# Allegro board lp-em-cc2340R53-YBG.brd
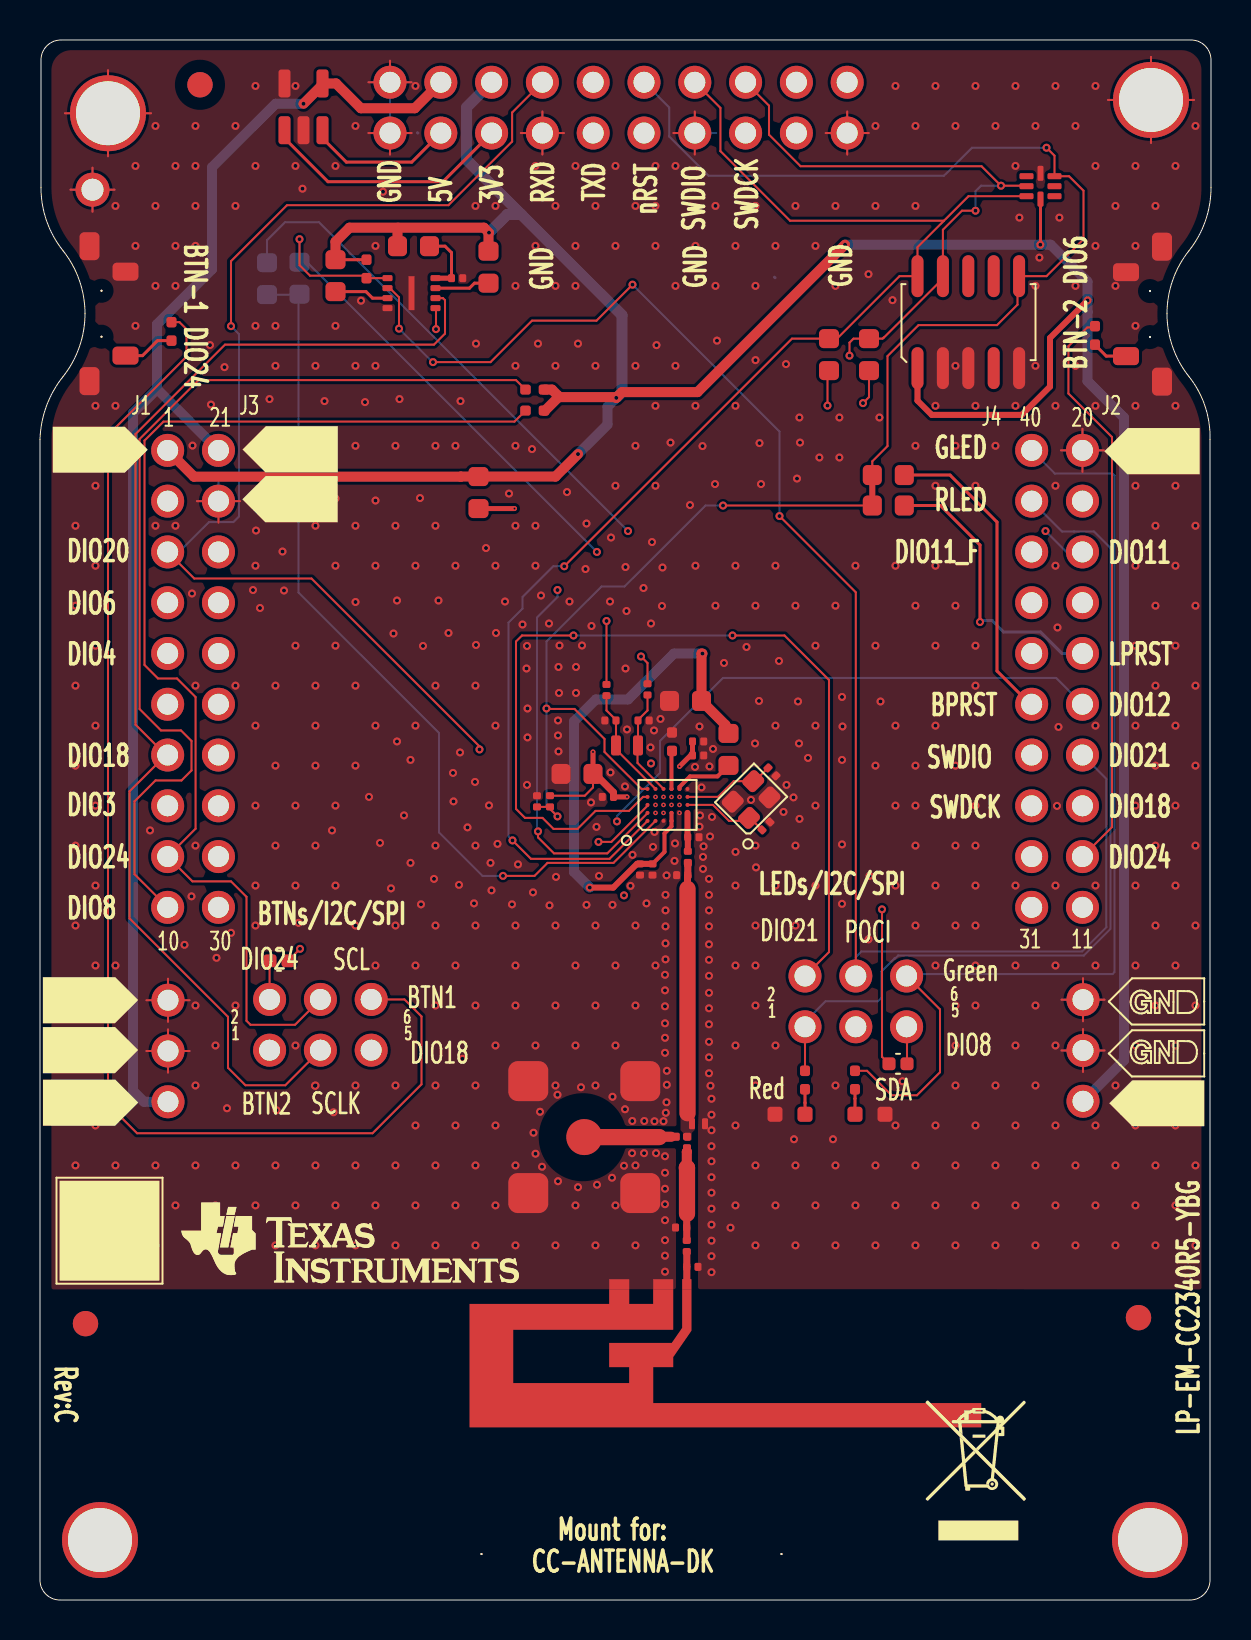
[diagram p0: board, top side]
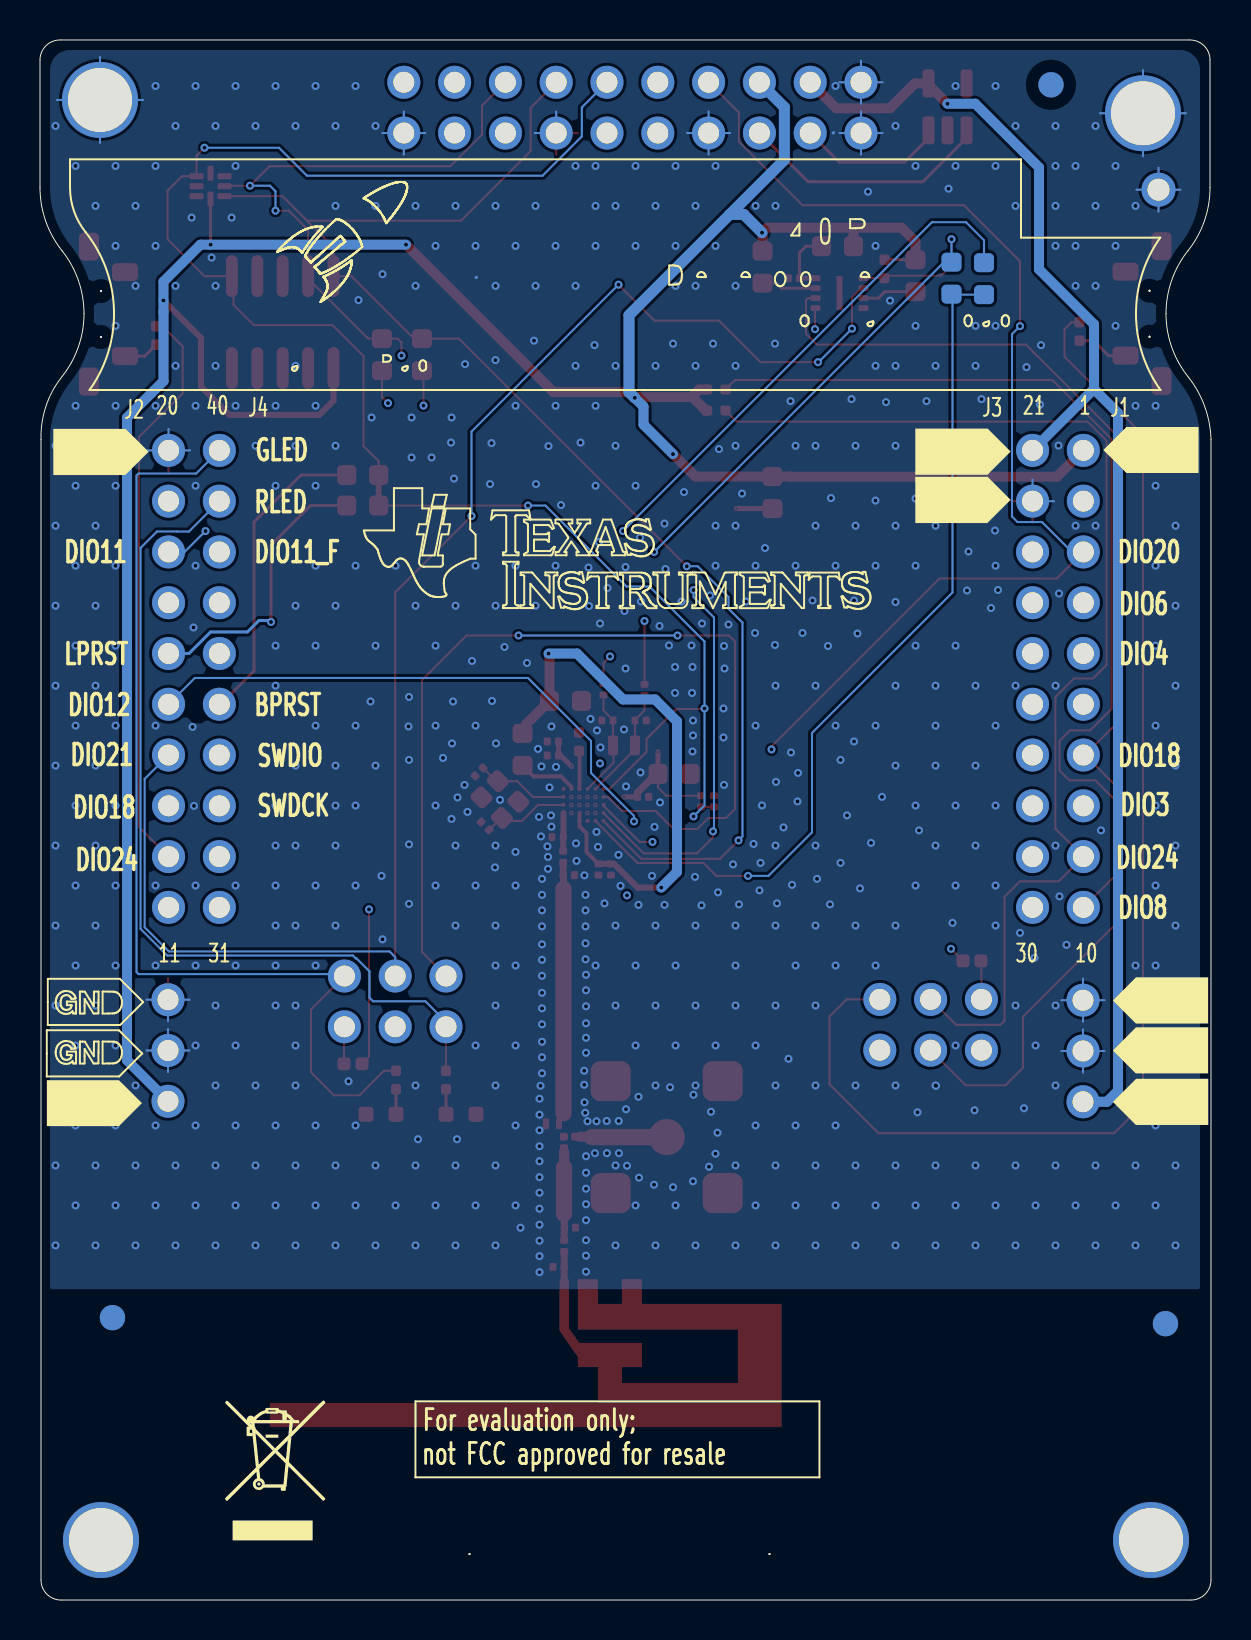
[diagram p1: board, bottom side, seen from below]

Outline 58.55 x 78.04 mm; copper layers: TOP, LAYER2, LAYER3, LAYER4, LAYER5, BOTTOM. Coordinates in mm from the lower left corner of the outline.
Outline path: 0,58.05 0,1 arc(0.29,0.29) 1,0 57.5,0 arc(58.21,0.29) 58.5,1 58.5,58.05 arc(58.25,59.72) 57.45,61.2 arc(56.63,62.68) 56.35,64.35 arc(56.63,66.02) 57.45,67.5 arc(58.27,68.98) 58.55,70.65 58.55,77.04 arc(58.26,77.75) 57.55,78.04 1.05,78.04 arc(0.34,77.75) 0.05,77.04 0.05,70.65 arc(0.33,68.98) 1.15,67.5 arc(1.97,66.02) 2.25,64.35 arc(1.97,62.68) 1.15,61.2 arc(0.32,59.72) 0,58.05

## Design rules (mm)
constraint set DEFAULT: min track width 0.102
net group BTN1: nets BTN1 N3110768
net group BTN2: nets BTN2 N3110772
net group DIO3: nets DIO3 X32_P
net group DIO4: nets DIO4 X32_N
net group DIO8_SDA: nets DIO8_SDA DIO8_SDA_T
net group DIO24_A7_SCL: nets DIO24_A7_SCL DIO24_A7_SCL_T
net group GLED: nets GLED N3110876
net group RLED: nets N3110880 RLED
net group WMCU_SWDCK: nets N3109960 WMCU_SWDCK
net group WMCU_SWDIO: nets N3109894 WMCU_SWDIO
net group BP_RESET: nets BP_RESET LP_RESET WMCU_RESET
net group DIO11_FLASH_CS: nets DIO11 DIO11_CS DIO11_FLASH_CS
net group RF: nets N3377070 RF RF_ANT RF_FILT RF_SMA

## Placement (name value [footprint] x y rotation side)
ANT1  2.4GHz  [ANTENNA_DN007AN]  32.34 15.8 180 top
B1  0  [RESC1608X55A2N]  21.93 54.6 90 top
C9  1uF  [CAPC1005X60B2N]  31.6 42.48 90 top
C33  1.5pF  [CAPC0603X35B2N]  32.95 38.16 180 top
C34  1.5pF  [CAPC0603X35B2N]  31.83 36.26 0 top
C52  7.5pF  [CAPC0603X35B2N]  36.1 38.53 45 top
C53  7.5pF  [CAPC0603X35B2N]  36.4 41.62 315 top
C55  0.1uF  [CAPC0603X35B2N]  20.57 66.12 0 top
C81  12pF  [CAPC0603X35B2N]  29.9 44 0 top
C91  15pF  [CAPC0603X35B2N]  28.8 44 180 top
C92  0.1uF  [CAPC0603X35B2N]  24.85 39.68 90 top
C101  0.1uF  [CAPC0603X35B2N]  32.62 42.95 0 top
C102  0.1uF  [CAPC0603X35B2N]  28.68 40.18 180 top
C103  0.1uF  [CAPC0603X35B2N]  32.62 42.25 0 top
C104  10uF  [CAPC1608X100A2N]  27.65 41.33 180 top
C105  10uF  [CAPC1608X100A2N]  33.07 44.98 180 top
C106  0.1uF  [CAPC0603X35B2N]  30.62 36.83 270 top
C107  0.1uF  [CAPC0603X35B2N]  30 36.83 270 top
CA1  15pF  [CAPC0603X35B2N]  32.38 23.18 180 top
CA2  15pF  [CAPC0603X35B2N]  32.35 22.62 90 top
CR1  LPL296-J2L2-25  [LEDC1707X65N]  42.25 24.3 180 top
CR2  LS L296-P2Q2-1  [LEDC1708X67N]  36.75 24.3 0 top
CR8  TPD6E004RSE  [QFNFC50P150X150X60-8A2N]  50.72 70.23 90 top
CR10  TPD1E0B04DPY  [SON65P100X60X45-2A2N]  33.25 23.83 180 top
FIDU1  FIDU_1.27mm  [FID127X142]  8 75.8 0 top
FIDU2  FIDU_1.27mm  [FID127X142]  2.28 13.83 0 top
FIDU3  FIDU_1.27mm  [FID127X142]  54.93 14.12 0 top
FIDU4  FIDU_1.27mm  [FID127X142]  8 75.8 180 bottom
FIDU5  FIDU_1.27mm  [FID127X142]  2.28 13.83 180 bottom
FIDU6  FIDU_1.27mm  [FID127X142]  54.93 14.12 180 bottom
J1  SSQ-110-23-L-D  [SAMTEC_SSQ11023LD_A2B]  6.38 57.51 0 bottom
J2  SSQ-110-23-L-D  [SAMTEC_SSQ11023LD_A2B]  49.58 57.51 0 bottom
J7  SMA-10V21-TGG  [HUSTSAN_SMA10V21TGGAN]  27.21 23.16 0 top
L1  10uH  [INDC1608X100A2N]  34.43 43.35 270 top
L33  2.8nH  [INDC0603X33A2N]  32.39 37.46 270 top
LBL1  TI_LOGO  [TI_LOGO_1]  8.06 19.89 0 top
LBL2  TRASH_7mm  [TRASH_7MM]  44.92 2.98 0 top
LBL3  ESD_LABEL_5x5mm  [ESD_LABEL_5X5]  0.97 15.98 0 top
LBL5  -  [LABEL_FOR_EVALUATION_ONLY]  39.63 6.29 180 bottom
M1  SNT-100-BK-G  [SAMTEC_SNT100BKG]  39.5 27.43 90 top
M2  SNT-100-BK-G  [SAMTEC_SNT100BKG]  44.6 27.38 90 top
M3  DCB-12D  [MECH_DCB12D_A2B]  3 3 0 top
M4  DCB-12D  [MECH_DCB12D_A2B]  55.5 3 0 top
M5  DCB-12D  [MECH_DCB12D_A2B]  3.38 75.2 0 top
M6  DCB-12D  [MECH_DCB12D_A2B]  55.53 75.04 0 top
M7  SNT-100-BK-G  [SAMTEC_SNT100BKG]  12.75 26.2 90 top
M8  SNT-100-BK-G  [SAMTEC_SNT100BKG]  17.82 26.2 90 top
MH1  HOLE_3.2mm_PAD_3.8mm_PTH  [MTG320_380]  3 3 0 top
MH2  HOLE_3.2mm_PAD_3.8mm_PTH  [MTG320_380]  55.5 3 0 top
MH3  HOLE_3.2mm_PAD_3.8mm_PTH  [MTG320_380]  3.4 74.38 0 top
MH4  HOLE_3.2mm_PAD_3.8mm_PTH  [MTG320_380]  55.55 75.04 0 top
MH5  HOLE_1.1mm_PTH  [MTG110_170]  2.62 70.55 0 top
NOREF  #VALUE  [unnamed]  22.07 2.3 0 top
NOREF#2  -  [#2]  0.05 75.03 0 top
NOREF#3  -  [#2]  -2.23 77.42 0 top
NOREF#4  -  [#2]  -2.31 22.34 0 top
NOREF#5  -  [#2]  0.9 -39.72 0 top
NOREF#6  -  [#2]  -4.3 56.35 0 top
NOREF#7  -  [#2]  0.28 64.51 0 top
NOREF#8  -  [#2]  53.24 23.47 0 top
NOREF#9  -  [#2]  -45.6 -63.8 0 top
NOREF#10  -  [#2]  53.15 0 90 top
NOREF#11  -  [#2]  8.4 52.65 0 top
NOREF#12  -  [#2]  51.5 55.05 0 top
NOREF#13  -  [#2]  -2.18 25.12 0 top
NOREF#14  -  [#2]  0.34 77.74 0 top
NOREF#15  -  [#2]  -2.18 27.62 0 top
NOREF#16  -  [#2]  8.46 55.02 0 top
NOREF#17  -  [#2]  60.2 55.05 180 bottom
NOREF#18  -  [#2]  6.57 22.38 180 bottom
NOREF#19  -  [#2]  17.24 54.91 180 bottom
NOREF#20  -  [#2]  58.27 23.64 180 bottom
NOREF#21  -  [#2]  6.62 25.08 180 bottom
NOREF#22  -  [#2]  6.62 27.58 180 bottom
NOREF#23  -  [#2]  116.69 68.47 180 bottom
NOREF#24  -  [#2]  51.53 78.57 180 bottom
NOREF#25  -  [#2]  5.6 56.15 180 bottom
NOREF#26  -  [#2]  17.1 52.65 180 bottom
P1  BB02-HC031-KB1-603000  [GRADCONN_BB02HC031KB1603000_A2B]  52.15 24.95 90 top
P2  BB02-HJ061-KB1-603000  [GRADCONN_BB02HJ061KB1603000_A2B]  38.25 28.68 0 top
P3  CNT-F254-210-GD-850/3.2  [CNT_CNTF254210GD85032_A2B]  17.5 75.93 0 top
P4  FTSH-105-01-F-DV-K  [SAMTEC_FTSH-105-01-F-DV-K-10N]  43.88 61.62 0 top
P5  BB02-HC031-KB1-603000  [GRADCONN_BB02HC031KB1603000_A2B]  6.4 24.93 90 top
P6  BB02-HJ061-KB1-603000  [GRADCONN_BB02HJ061KB1603000_A2B]  11.48 27.51 0 top
R1  100k  [RESC0603X35B2N]  25.5 39.68 90 top
R4  0  [RESC1608X55A2N]  39.45 61.5 90 top
R5  0  [RESC1608X55A2N]  41.45 61.5 90 top
R6  0  [RESC0603X35B2N]  30.38 45.28 90 top
R7  0  [RESC0603X35B2N]  28.32 45.8 270 top
R14  180  [RESC1005X40B2N]  38.25 25.55 90 top
R15  220  [RESC1005X40B2N]  40.75 25.55 90 top
R19  0  [RESC1608X55A2N]  11.35 65.3 90 bottom
R20  0  [RESC1608X55A2N]  12.97 65.33 90 bottom
R22  0  [RESC1608X55A2N]  22.43 67.48 270 top
R23  0  [RESC1608X55A2N]  14.78 67.05 270 top
R24  2.2k  [RESC1005X40B2N]  16.32 66.12 90 top
R25  0  [RESC1608X55A2N]  19.47 67.73 180 top
R51  0  [RESC1608X55A2N]  43.22 54.75 180 top
R52  0  [RESC1608X55A2N]  43.22 56.28 180 top
R55  100  [RESC1005X40B2N]  52.75 62.8 90 top
R56  100  [RESC1005X40B2N]  6.57 63 90 top
R66  3.3k  [RESC1005X40B2N]  24.28 60.55 0 top
R67  3.3k  [RESC1005X40B2N]  24.28 59.5 0 top
R68  0  [RESC1005X40A2N]  11.5 31.98 0 top
R69  0  [RESC1005X40A2N]  42.45 26.83 0 top
SW1  1188E-1K2  [SW_1188E1K2V_A2N]  2.47 67.73 270 top
SW2  1188E-1K2  [SW_1188E1K2V_A2N]  56.1 60.95 90 top
U1  CC2340R53E0YBG  [BGAFC28C40P260X219X50]  30.38 38.98 0 top
U3  MX25R8035FZUIL0  [SON50P300X200X60-9B2N]  17.38 66.12 270 top
U4  CAT24C08TDI  [SOT95P280X100-5A2N]  12.22 73.53 0 top
UNK#REFDES  #VALUE  [#2]  46.65 66.21 180 bottom
Y1  32.768KHz  [XTAL_TZ3359DAAO73_A2N]  29.9 42.75 180 top
Y2  48MHz  [OSCCC205X165X50-4A2N]  35.45 39.12 45 top
Z60  12pF  [CAPC0603X35B2N]  32.34 18.63 180 top
Z61  0  [RESC0603X35B2N]  32.34 17.43 90 top
Z62  12pF  [CAPC0603X35B2N]  32.34 16.67 0 top

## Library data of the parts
ANT1 = ANTENNA_DN007
B1 R4 R5 R19 R20 R22 R23 R25 R51 R52 = RESISTOR: User Part Number: #PN; alternate symbols: (RESC1608X55A2L,RESC1608X55A2M)
C9 = CAPACITOR: User Part Number: #PN; alternate symbols: (CAPC1005X60A2L,CAPC1005X60A2M)
C33 C34 C52 C53 C55 C81 C91 C92 C101-C103 C106 C107 CA1 CA2 Z60 Z62 = CAPACITOR: User Part Number: #PN; alternate symbols: (CAPC0603X35B2L,CAPC0603X35B2M)
C104 C105 = CAPACITOR: User Part Number: #PN; alternate symbols: (CAPC1608X100A2L,CAPC1608X100A2M)
CR1 = LED: alternate symbols: (LEDC1707X65L,LEDC1707X65M)
CR2 = LED: alternate symbols: (LEDC1708X67L,LEDC1708X67M)
CR8 = DIODE_TVS_TPD6E004_QFN8_V1: User Part Number: #PN; alternate symbols: (QFNFC50P150X150X60-8A2L,QFNFC50P150X150X60-8A2M)
CR10 = DIODE_TVS_BIDIR_S_0: User Part Number: #PN
FIDU1-FIDU6 = FIDMARK
J1 J2 = CONN_HEADER_2X10_J_S_V1: User Part Number: #PN; alternate symbols: (SAMTEC_SSQ11023LD_A2A,SAMTEC_SSQ11023LD_A2C)
J7 = CONN_COAX_1_4: alternate symbols: (HUSTSAN_SMA10V21TGGL,HUSTSAN_SMA10V21TGGM)
L1 = IND_CORE: User Part Number: #PN; alternate symbols: (INDC1608X100A2L,INDC1608X100A2M)
L33 = INDUCTOR: User Part Number: #PN; alternate symbols: (INDC0603X33A2L,INDC0603X33A2M)
LBL1 = TI_LOGO_V1
LBL2 = TRASH_V2: User Part Number: #PN
LBL3 = ESD_LABEL: User Part Number: #PN
LBL5 = LABEL_FOR_EVALUATOIN_ONLY: User Part Number: #PN
M1 M2 M7 M8 = MECH_SHUNT_JUMPER_V1: User Part Number: #PN
M3-M6 = MECH_SPACERS_SUPPORT_V1: User Part Number: #PN
MH1-MH5 = HOLE_PTH
NOREF UNK#REFDES = -: User Part Number: #PN
P1 P5 = CONN_HEADER_3_P_S: User Part Number: #PN; alternate symbols: (GRADCONN_BB02HC031KB1603000_A2A,GRADCONN_BB02HC031KB1603000_A2C)
P2 P6 = CONN_HEADER_2X3_P_V2: User Part Number: #PN; alternate symbols: (GRADCONN_BB02HJ061KB1603000_A2A,GRADCONN_BB02HJ061KB1603000_A2C)
P3 = CONN_HEADER_2X10_J_S_V1: User Part Number: #PN; alternate symbols: (CNT_CNTF254210GD85032_A2A,CNT_CNTF254210GD85032_A2C)
P4 = CONN_HEADER_2X5: alternate symbols: (SAMTEC_FTSH10501FDVK_A2L,SAMTEC_FTSH10501FDVK_A2M,SAMTEC_FTSH10501FDVK_B2L,SAMTEC_FTSH10501FDVK_B2M)
R1 R6 R7 Z61 = RESISTOR: User Part Number: #PN; alternate symbols: (RESC0603X35B2L,RESC0603X35B2M)
R14 R15 R24 R55 R56 R66 R67 = RESISTOR: User Part Number: #PN
R68 R69 = RESISTOR: User Part Number: #PN; alternate symbols: (RESC1005X40A2L,RESC1005X40A2M)
SW1 SW2 = SWITCH_TACT_V2: alternate symbols: (SW_1188E1K2V_A2L,SW_1188E1K2V_A2M)
U1 = IC_CC2340R5_DSBGA28_V1: User Part Number: #PN
U3 = IC_FLASH_MX25R8035F_USON8: User Part Number: #PN; alternate symbols: (SON50P300X200X60-9B2L,SON50P300X200X60-9B2M)
U4 = IC_EEPROM_CAT24C08_TSOT23-5: User Part Number: #PN; alternate symbols: (SOT95P280X100-5A2L,SOT95P280X100-5A2M)
Y1 = XTAL: User Part Number: #PN; alternate symbols: (XTAL_TZ3359DAAO73_A2L,XTAL_TZ3359DAAO73_A2M)
Y2 = XTAL_4PINS_1_3: User Part Number: #PN; alternate symbols: (OSCCC205X165X50-4A2L,OSCCC205X165X50-4A2M)

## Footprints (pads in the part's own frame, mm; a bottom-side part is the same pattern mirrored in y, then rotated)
ANTENNA_DN007AN
  rect 0.46x0.5 smd: 1(0,0)
  rect 1x0.5 smd: 2(1.18,0) 3(3.38,0)
BGAFC28C40P260X219X50
  round 0.2 smd: A1(0,0) A2(0,0.4) A3(0,0.8) A4(0,1.2) A5(0,1.6) B1(0.4,0) B2(0.4,0.4) B3(0.4,0.8) B4(0.4,1.2) B5(0.4,1.6) C1(0.8,0) C2(0.8,0.4) C3(0.8,0.8) C4(0.8,1.2) C5(0.8,1.6) D1(1.2,0) D2(1.2,0.4) D3(1.2,0.8) D4(1.2,1.2) D5(1.2,1.6) E2(1.6,0.4) E3(1.6,0.8) E4(1.6,1.2) E5(1.6,1.6) F2(2,0.4) F3(2,0.8) F4(2,1.2) F5(2,1.6)
CAPC0603X35B2N
  custom 0.087x0.087 smd: 1(0,0) 2(0.56,0)
CAPC1005X60B2N
  custom 0.125x0.125 smd: 1(0,0) 2(0.924,0)
CAPC1608X100A2N
  custom 0.237x0.237 smd: 1(0,0) 2(1.6,0)
CNT_CNTF254210GD85032_A2B
  round 1.65 hole 1.05: 1(0,0) 2(0,-2.54) 3(2.54,0) 4(2.54,-2.54) 5(5.08,0) 6(5.08,-2.54) 7(7.62,0) 8(7.62,-2.54) 9(10.16,0) 10(10.16,-2.54) 11(12.7,0) 12(12.7,-2.54) 13(15.24,0) 14(15.24,-2.54) 15(17.78,0) 16(17.78,-2.54) 17(20.32,0) 18(20.32,-2.54) 19(22.86,0) 20(22.86,-2.54)
FID127X142
  round 1.27 smd: 1(0,0)
GRADCONN_BB02HC031KB1603000_A2B
  round 1.65 hole 1.05: 1(0,0) 2(2.54,0) 3(5.08,0)
GRADCONN_BB02HJ061KB1603000_A2B
  round 1.65 hole 1.05: 1(0,0) 2(0,2.54) 3(2.54,0) 4(2.54,2.54) 5(5.08,0) 6(5.08,2.54)
HUSTSAN_SMA10V21TGGAN
  round 1.8 smd: 1(0,0)
  custom 0.5x0.5 smd: 2(-2.8,-2.8) 3(2.8,-2.8) 4(2.8,2.8) 5(-2.8,2.8)
INDC0603X33A2N
  custom 0.087x0.087 smd: 1(0,0) 2(0.56,0)
INDC1608X100A2N
  custom 0.237x0.237 smd: 1(0,0) 2(1.6,0)
LEDC1707X65N
  custom 0.188x0.188 smd: 1(0,0) 2(1.501,0)
LEDC1708X67N
  custom 0.188x0.188 smd: 1(0,0) 2(1.501,0)
MTG110_170
  round 1.7 hole 1.1: 1(0,0)
MTG320_380
  round 3.8 hole 3.2: 1(0,0)
OSCCC205X165X50-4A2N
  custom 0.212x0.212 smd: 1(0,0) 2(1.45,0) 3(1.45,1.15) 4(0,1.15)
QFNFC50P150X150X60-8A2N
  custom 0.075x0.075 smd: 1(0,0) 2(0.5,0) 3(1,0) 4(1.145,0.7) 5(1,1.4) 6(0.5,1.4) 7(0,1.4) 8(-0.145,0.7)
RESC0603X35B2N
  custom 0.087x0.087 smd: 1(0,0) 2(0.56,0)
RESC1005X40A2N
  custom 0.16x0.16 smd: 1(0,0) 2(0.9,0)
RESC1005X40B2N
  custom 0.125x0.125 smd: 1(0,0) 2(0.924,0)
RESC1608X55A2N
  custom 0.237x0.237 smd: 1(0,0) 2(1.6,0)
SAMTEC_FTSH-105-01-F-DV-K-10N
  oval 0.6x2.1 smd: 1(0,0) 2(0,4.6) 3(1.27,0) 4(1.27,4.6) 5(2.54,0) 6(2.54,4.6) 7(3.81,0) 8(3.81,4.6) 9(5.08,0) 10(5.08,4.6)
SAMTEC_SSQ11023LD_A2B
  round 1.65 hole 1.05: 1(0,0) 2(2.54,0) 3(0,2.54) 4(2.54,2.54) 5(0,5.08) 6(2.54,5.08) 7(0,7.62) 8(2.54,7.62) 9(0,10.16) 10(2.54,10.16) 11(0,12.7) 12(2.54,12.7) 13(0,15.24) 14(2.54,15.24) 15(0,17.78) 16(2.54,17.78) 17(0,20.32) 18(2.54,20.32) 19(0,22.86) 20(2.54,22.86)
SON50P300X200X60-9B2N
  custom 0.075x0.075 smd: 1(0,0) 2(0.5,0) 3(1,0) 4(1.5,0) 5(1.5,2.4) 6(1,2.4) 7(0.5,2.4) 8(0,2.4)
  rect 1.7x0.3 smd: 9(0.75,1.2)
SON65P100X60X45-2A2N
  custom 0.075x0.075 smd: 1(0,0) 2(0.65,0)
SOT95P280X100-5A2N
  custom 0.15x0.15 smd: 1(0,0) 2(0.95,0) 3(1.9,0) 4(1.9,2.34) 5(0,2.34)
SW_1188E1K2V_A2N
  round 0.1 hole 0.9 unplated: (2.229,0.6) (4.529,0.6)
  custom 0.25x0.25 smd: 1(0,0) 2(6.75,0)
  custom 0.225x0.225 smd: 3(1.275,1.8) 4(5.475,1.8)
unnamed
  round 0.1 hole 3.2 unplated: (0,0) (15,0)
XTAL_TZ3359DAAO73_A2N
  custom 0.125x0.125 smd: 1(0,0) 2(1.1,0)

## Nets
5V0_BP: J1.2 P3.3 P5.1 U4.4
GND: ANT1.2 ANT1.3(\GND_3\) C9.2 C33.1 C34.1 C52.2 C53.2 C55.2 C81.2 C91.2 C92.2 C101.2 C102.2 C103.2 C104.2 C105.2 C106.2 C107.2 CR1.1(\C\) CR2.1(\C\) CR8.4 CR10.1 J1.4 J2.2 J7.2 J7.3 J7.4 J7.5 MH3.1 MH4.1 MH5.1 P1.2 P1.3 P3.1 P3.2 P3.8 P3.14 P3.20 P4.3 P4.5 P4.9 P5.2 P5.3 SW1.1 SW1.2 SW1.3 SW2.1 SW2.2 SW2.4 U1.C1 U1.C3 U1.D4 U1.E2 U1.F5 U3.4 U3.9 U4.2 U4.5(\WP\) Y2.2 Y2.4(\GND#4\) Z60.2 Z62.2
VDDD: C9.1 U1.D5
VDDR: C105.1 C106.1 C107.1 L1.1 U1.D1 U1.D2
VDDS: B1.1 C101.1 C102.1 C103.1 C104.1 R1.2 U1.B4 U1.E3 U1.E4
BP_RESET: J2.11 R52.1
BTN1: J2.16 P6.6 R56.2
BTN2: J2.18 P6.1 R55.2
DCDC: L1.2 U1.E5
DIO3: J1.15 R6.2
DIO4: J1.9 R7.1
DIO8_SDA: P2.5 R69.2
DIO8_SDA_T: R69.1 U1.C2(\DIO8\)
DIO11: R19.1 R20.1 U1.B1
DIO11_CS: J2.6 R19.2
DIO11_FLASH_CS: J2.5 R20.2 R24.1 U3.1
DIO12_PICO: J2.12 U1.B2 U3.5
DIO18_SCLK: P6.5 U1.B3
DIO21_A10_POCI: P2.2 U1.A4
DIO24_A7_SCL: P6.2 R68.1
DIO24_A7_SCL_T: R68.2 U1.C4
GLED: J2.1 P2.6 R15.2
LP_RESET: J2.10 R51.1
POCI: J2.14 P2.4 U3.2
RF: C33.2 L33.1 U1.F2
RF_ANT: CA2.1 Z60.1 Z61.2
RF_FILT: C34.2 CA1.1 CA2.2 CR10.2 L33.2
RF_SMA: CA1.2 J7.1
RLED: J2.3 P2.1 R14.2
SCL: J1.17 P6.4 R67.1
SCLK: J1.13 P6.3 U3.6
SDA: J1.19 P2.3 R66.1
WMCU_RESET: C92.1 CR8.3 P3.11 P4.10 R1.1 R51.2 R52.2 U1.A5
WMCU_RXD: J1.5 P3.7 U1.A3
WMCU_SWDCK: CR8.6 P3.15 P4.4 R5.2 U1.A2
WMCU_SWDIO: CR8.7 P3.13 P4.2 R4.2 U1.A1
WMCU_TXD: J1.7 P3.9 U1.D3
WMCU_VDD: B1.2 CR8.8(\VCC\) J1.1 P1.1 P3.5 P4.1 R22.1 R23.1 R24.2 R25.2 R66.2 R67.2
X32_N: C91.1 R7.2 U1.B5 Y1.2
X32_P: C81.1 R6.1 U1.C5 Y1.1
X48_N: C52.1 U1.F3 Y2.1
X48_P: C53.1 U1.F4 Y2.3
XDS_BOARDID_SCL: P3.6 U4.1
XDS_BOARDID_SDA: P3.4 U4.3
N3109894: J2.13 R4.1
N3109960: J2.15 R5.1
N3110768: R56.1 SW1.4
N3110772: R55.1 SW2.3
N3110876: CR1.2 R15.1
N3110880: CR2.2 R14.1
N3111246: C55.1 R25.1 U3.8(\VCC\)
N3111262: R22.2 U3.7
N3111266: R23.2 U3.3
N3377070: ANT1.1 Z61.1 Z62.1

Pads without a net: CR8 1 2 5; FIDU1 1; FIDU2 1; FIDU3 1; FIDU4 1; FIDU5 1; FIDU6 1; J1 3 6 8 10 11 12 14 16 18 20; J2 4 7 8 9 17 19 20; MH1 1; MH2 1; P3 10 12 16 17 18 19; P4 6 7 8

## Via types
v1: diameter 0.4, hole 0.2, TOP to BOTTOM, 722 vias
v2: diameter 0.23, hole 0.1, TOP to LAYER2, 15 vias
v3: diameter 0.23, hole 0.1, LAYER2 to LAYER3, 10 vias

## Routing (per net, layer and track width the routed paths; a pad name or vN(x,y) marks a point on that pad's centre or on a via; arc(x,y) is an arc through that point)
5V0_BP: length 68.4
  TOP w0.5: P3.3 18.74,74.62 16.04,74.62 14.8,75.87 U4.4 14.12,75.8 v1(13.18,74.85)
  BOTTOM w0.5: P5.1 5.2,24.93 4.65,25.47 4.65,59.38 5.85,60.58 5.85,60.58 ; v1(13.18,74.85) 11.78,74.85 8.6,71.67 8.6,66.57 5.85,63.82 5.85,60.58 ; 5.85,60.58 J1.2
GND: length 402.3
  TOP w0.102: P5.3 7.48,30.01 ; P5.3 6.4,31.08 ; P5.3 6.4,28.93 ; P5.3 5.32,30.01 ; MH4.1 57.7,75.04 ; MH4.1 53.4,75.04 ; MH4.1 55.55,72.89 ; MH4.1 55.55,77.19 ; 24.04,73.38 P3.8 ; P3.8 25.12,74.46 ; P3.8 26.2,73.38 ; P3.8 25.12,72.31 ; 3.4,72.22 MH3.1 ; MH3.1 5.55,74.38 ; MH3.1 1.25,74.38 ; MH3.1 3.4,76.53 ; P1.2 53.23,27.49 ; P1.2 51.07,27.49 ; P1.2 52.15,26.41 ; P1.2 52.15,28.57 ; J2.2 53.2,57.51 ; J2.2 52.12,56.43 ; J2.2 51.05,57.51 ; J2.2 52.12,58.59 ; 29.62,23.98 29.61,23.96 v1(29.61,23.96) ; J1.4 10,54.97 ; J1.4 7.85,54.97 ; J1.4 8.92,53.89 ; P3.14 32.74,74.46 ; P3.14 32.74,72.31 ; P3.14 31.66,73.38 ; MH5.1 3.73,70.55 ; MH5.1 2.62,71.65 ; MH5.1 1.52,70.55 ; MH5.1 2.62,69.45 ; 6.4,26.39 P5.2 ; P5.2 7.48,27.47 ; P5.2 5.32,27.47 ; P5.2 6.4,28.54 ; P1.3 53.23,30.03 ; P1.3 52.15,28.95 ; P1.3 51.07,30.03 ; P1.3 52.15,31.11 ; P3.20 40.36,74.46 ; P3.20 40.36,72.31 ; P3.20 41.44,73.38 ; P3.20 39.28,73.38 ; 17.5,72.31 P3.2 ; P3.2 16.42,73.38 ; P3.2 18.58,73.38 ; P3.1 18.58,75.93 ; P3.1 16.42,75.93 ; P3.1 17.5,77
  LAYER2 w0.102: 39.28,73.38 P3.20 ; P3.20 41.44,73.38 ; P3.20 40.36,74.46 ; P3.20 40.36,72.31 ; v2(31.97,39.38) 31.57,39.38 v3(31.18,39.78) v2(31.57,40.18) ; P3.14 32.74,74.46 ; P3.14 31.66,73.38 ; P3.14 33.82,73.38 ; P3.14 32.74,72.31 ; 25.12,72.31 P3.8 ; P3.8 24.04,73.38 ; P3.8 25.12,74.46 ; P3.8 26.2,73.38 ; 52.15,28.95 P1.3 ; P1.3 53.23,30.03 ; P1.3 51.07,30.03 ; P1.3 52.15,31.11 ; J1.4 8.92,56.05 ; J1.4 10,54.97 ; J1.4 7.85,54.97 ; J1.4 8.92,53.89 ; J2.2 53.2,57.51 ; J2.2 52.12,56.43 ; J2.2 52.12,58.59 ; J2.2 51.05,57.51 ; MH3.1 5.55,74.38 ; MH3.1 1.25,74.38 ; MH3.1 3.4,76.53 ; MH3.1 3.4,72.22 ; MH5.1 3.73,70.55 ; MH5.1 1.52,70.55 ; MH5.1 2.62,69.45 ; MH5.1 2.62,71.65 ; P5.3 6.4,31.08 ; P5.3 7.48,30.01 ; P5.3 5.32,30.01 ; P5.3 6.4,28.93 ; P5.2 6.4,28.54 ; P5.2 6.4,26.39 ; P5.2 5.32,27.47 ; P5.2 7.48,27.47 ; MH4.1 57.7,75.04 ; MH4.1 53.4,75.04 ; MH4.1 55.55,72.89 ; MH4.1 55.55,77.19 ; P3.1 17.5,77 ; P3.1 18.58,75.93 ; P3.1 16.42,75.93 ; P3.1 17.5,74.85 ; P3.2 17.5,74.46 ; P3.2 16.42,73.38 ; P3.2 17.5,72.31 ; P3.2 18.58,73.38 ; P1.2 53.23,27.49 ; P1.2 51.07,27.49 ; P1.2 52.15,28.57 ; P1.2 52.15,26.41
  LAYER3 w0.102: P5.3 6.4,31.08 ; P5.3 5.32,30.01 ; P5.3 7.48,30.01 ; P5.3 6.4,28.93 ; 16.42,75.93 P3.1 ; P3.1 17.5,77 ; P3.1 17.5,74.85 ; P3.1 18.58,75.93 ; MH3.1 5.55,74.38 ; MH3.1 1.25,74.38 ; MH3.1 3.4,76.53 ; MH3.1 3.4,72.22 ; P3.8 26.2,73.38 ; P3.8 24.04,73.38 ; P3.8 25.12,72.31 ; P3.8 25.12,74.46 ; 51.05,57.51 J2.2 ; J2.2 53.2,57.51 ; J2.2 52.12,58.59 ; J2.2 52.12,56.43 ; P3.2 17.5,74.46 ; P3.2 16.42,73.38 ; P3.2 17.5,72.31 ; P3.2 18.58,73.38 ; P3.20 41.44,73.38 ; P3.20 39.28,73.38 ; P3.20 40.36,74.46 ; P3.20 40.36,72.31 ; MH5.1 3.73,70.55 ; MH5.1 2.62,69.45 ; MH5.1 2.62,71.65 ; MH5.1 1.52,70.55 ; P3.14 33.82,73.38 ; P3.14 32.74,74.46 ; P3.14 32.74,72.31 ; P3.14 31.66,73.38 ; MH4.1 57.7,75.04 ; MH4.1 55.55,72.89 ; MH4.1 55.55,77.19 ; MH4.1 53.4,75.04 ; 7.85,54.97 J1.4 ; J1.4 8.92,56.05 ; J1.4 10,54.97 ; J1.4 8.92,53.89 ; 52.15,26.41 P1.2 ; P1.2 51.07,27.49 ; P1.2 52.15,28.57 ; P1.2 53.23,27.49 ; P5.2 7.48,27.47 ; P5.2 5.32,27.47 ; P5.2 6.4,26.39 ; P5.2 6.4,28.54 ; 52.15,28.95 P1.3 ; P1.3 51.07,30.03 ; P1.3 53.23,30.03 ; P1.3 52.15,31.11
  LAYER4 w0.102: 1.25,74.38 MH3.1 ; MH3.1 5.55,74.38 ; MH3.1 3.4,72.22 ; MH3.1 3.4,76.53 ; 17.5,72.31 P3.2 ; P3.2 17.5,74.46 ; P3.2 16.42,73.38 ; P3.2 18.58,73.38 ; P3.20 41.44,73.38 ; P3.20 40.36,74.46 ; P3.20 39.28,73.38 ; P3.20 40.36,72.31 ; 25.12,72.31 P3.8 26.2,73.38 ; J1.4 8.92,56.05 ; J1.4 8.92,53.89 ; J1.4 10,54.97 ; J1.4 7.85,54.97 ; P3.1 18.58,75.93 ; P3.1 16.42,75.93 ; P3.1 17.5,77 ; P3.1 17.5,74.85 ; 5.32,27.47 P5.2 ; P5.2 7.48,27.47 ; P5.2 6.4,26.39 ; P5.2 6.4,28.54 ; 52.12,56.43 J2.2 ; J2.2 52.12,58.59 ; J2.2 51.05,57.51 ; J2.2 53.2,57.51 ; 5.32,30.01 P5.3 ; P5.3 6.4,28.93 ; P5.3 7.48,30.01 ; P5.3 6.4,31.08 ; 52.15,28.95 P1.3 ; P1.3 51.07,30.03 ; P1.3 52.15,31.11 ; P1.3 53.23,30.03 ; P3.14 32.74,74.46 ; P3.14 32.74,72.31 ; P3.14 31.66,73.38 ; P3.14 33.82,73.38 ; MH4.1 57.7,75.04 ; MH4.1 55.55,77.19 ; MH4.1 53.4,75.04 ; MH4.1 55.55,72.89 ; 52.15,26.41 P1.2 ; P1.2 52.15,28.57 ; P1.2 51.07,27.49 ; P1.2 53.23,27.49 ; MH5.1 3.73,70.55 ; MH5.1 2.62,71.65 ; MH5.1 1.52,70.55 ; MH5.1 2.62,69.45
  LAYER5 w0.102: P3.8 25.12,74.46 ; P3.8 25.12,72.31 ; P3.8 26.2,73.38 ; P3.8 24.04,73.38 ; 53.4,75.04 MH4.1 ; MH4.1 57.7,75.04 ; MH4.1 55.55,72.89 ; MH4.1 55.55,77.19 ; P3.20 41.44,73.38 ; P3.20 39.28,73.38 ; P3.20 40.36,72.31 ; P3.20 40.36,74.46 ; 8.92,53.89 J1.4 ; J1.4 8.92,56.05 ; J1.4 10,54.97 ; J1.4 7.85,54.97 ; 51.05,57.51 J2.2 ; J2.2 52.12,56.43 ; J2.2 52.12,58.59 ; J2.2 53.2,57.51 ; P1.2 52.15,28.57 ; P1.2 51.07,27.49 ; P1.2 53.23,27.49 ; P1.2 52.15,26.41 ; P3.1 18.58,75.93 ; P3.1 17.5,74.85 ; P3.1 17.5,77 ; P3.1 16.42,75.93 ; 17.5,72.31 P3.2 ; P3.2 16.42,73.38 ; P3.2 18.58,73.38 ; P3.2 17.5,74.46 ; P5.2 6.4,28.54 ; P5.2 7.48,27.47 ; P5.2 6.4,26.39 ; P5.2 5.32,27.47 ; 52.15,28.95 P1.3 ; P1.3 51.07,30.03 ; P1.3 52.15,31.11 ; P1.3 53.23,30.03 ; MH5.1 2.62,71.65 ; MH5.1 3.73,70.55 ; MH5.1 2.62,69.45 ; MH5.1 1.52,70.55 ; P3.14 32.74,74.46 ; P3.14 32.74,72.31 ; P3.14 31.66,73.38 ; P3.14 33.82,73.38 ; 1.25,74.38 MH3.1 ; MH3.1 5.55,74.38 ; MH3.1 3.4,76.53 ; MH3.1 3.4,72.22 ; P5.3 7.48,30.01 ; P5.3 6.4,31.08 ; P5.3 5.32,30.01 ; P5.3 6.4,28.93
  BOTTOM w0.102: 2.62,69.45 MH5.1 ; MH5.1 2.62,71.65 ; MH5.1 1.52,70.55 ; MH5.1 3.73,70.55 ; P3.2 18.58,73.38 ; P3.2 16.42,73.38 ; P3.2 17.5,72.31 ; P3.2 17.5,74.46 ; 6.4,26.39 P5.2 ; P5.2 5.32,27.47 ; P5.2 6.4,28.54 ; P5.2 7.48,27.47 ; 16.42,75.93 P3.1 ; P3.1 18.58,75.93 ; P3.1 17.5,74.85 ; P3.1 17.5,77 ; P3.20 41.44,73.38 ; P3.20 40.36,74.46 ; P3.20 39.28,73.38 ; P3.20 40.36,72.31 ; J2.2 53.2,57.51 ; J2.2 51.05,57.51 ; J2.2 52.12,58.59 ; MH4.1 57.7,75.04 ; MH4.1 55.55,77.19 ; MH4.1 53.4,75.04 ; MH4.1 55.55,72.89 ; P1.2 52.15,28.57 ; P1.2 52.15,26.41 ; P1.2 53.23,27.49 ; P1.2 51.07,27.49 ; 24.04,73.38 P3.8 ; P3.8 26.2,73.38 ; P3.8 25.12,74.46 ; P3.8 25.12,72.31 ; 6.4,28.93 P5.3 ; P5.3 6.4,31.08 ; P5.3 7.48,30.01 ; P5.3 5.32,30.01 ; 32.74,74.46 P3.14 33.82,73.38 ; MH3.1 3.4,76.53 ; MH3.1 5.55,74.38 ; MH3.1 3.4,72.22 ; MH3.1 1.25,74.38 ; P1.3 53.23,30.03 ; P1.3 51.07,30.03 ; P1.3 52.15,28.95 ; 7.85,54.97 J1.4 8.92,56.05
  BOTTOM w0.15: 18.89,73.38 18.88,73.4 ; 36.72,66.18 36.75,66.15
  vias: v1(1.77,57.74) v1(1.77,53.74) v1(1.77,49.74) v1(1.77,45.74) v1(1.77,41.74) v1(1.77,37.74) v1(1.77,33.74) v1(1.77,29.74) v1(1.77,25.74) v1(1.77,21.74) v1(1.77,17.74) v1(2.77,59.74) v1(2.77,55.74) v1(2.77,51.74) v1(2.77,47.74) v1(2.77,43.74) v1(2.77,39.74) v1(2.77,35.74) v1(2.77,31.74) v1(2.77,27.74) v1(2.77,23.74) v1(2.77,19.74) v1(3.77,69.74) v1(3.77,59.74) v1(3.77,31.74) v1(3.77,27.74) v1(3.77,21.74) v1(3.77,17.74) v1(4.77,71.74) v1(4.77,67.74) v1(4.77,63.74) v1(4.77,19.74) v1(5.5,38.5) v1(5.77,73.74) v1(5.77,69.74) v1(5.77,65.74) v1(5.77,53.74) v1(5.77,21.74) v1(5.77,17.74) v1(6.77,71.74) v1(6.77,67.74) v1(6.77,65.74) v1(6.77,53.74) v1(6.77,19.74) v1(7.22,32.78) v1(7.62,57.75) v1(7.6,50.35) v1(7.57,35.2) v1(7.77,73.74) v1(7.77,71.74) v1(7.77,69.74) v1(7.77,67.74) v1(7.77,45.74) v1(7.77,37.74) v1(7.77,29.74) v1(7.77,25.74) v1(7.77,21.74) v1(7.77,17.74) v1(8.5,62.78) v1(8.55,59.8) v1(8.82,32.12) v1(8.77,27.74) v1(8.77,19.74) v1(9.22,61.68) v1(9.35,24.6) v1(9.55,33.38) v1(9.77,73.74) v1(9.77,69.74) v1(9.77,45.74) v1(9.77,29.74) v1(9.77,21.74) v1(9.77,17.74) v1(10.65,50.53) v1(10.77,75.74) v1(10.77,71.74) v1(10.77,63.74) v1(10.8,53.5) v1(10.77,51.74) v1(10.77,43.74) v1(10.77,39.74) v1(10.77,35.74) v1(10.77,33.74) v1(10.77,19.74) v1(11,49.62) v1(11.47,60.08) v1(11.77,63.74) v1(11.77,61.74) v1(11.77,57.74) v1(11.77,45.74) v1(11.77,41.74) v1(11.77,37.74) v1(11.82,24.5) v1(11.77,21.74) v1(11.77,17.74) v1(11.97,54.45) v1(12.12,52.45) v1(12.2,50.5) v1(12.77,75.74) v1(12.77,71.74) v1(12.77,47.74) v1(12.77,39.74) v1(12.77,35.74) v1(12.77,27.74) v1(12.77,19.74) v1(12.93,33.88) v1(13.12,70.6) v1(13.77,61.74) v1(13.77,57.74) v1(13.77,53.74) v1(13.77,45.74) v1(13.77,43.74) v1(13.77,41.74) v1(13.77,37.74) v1(13.77,25.74) v1(13.75,25.73) v1(13.77,21.74) v1(13.77,17.74) v1(14.22,59.98) v1(14.6,38.5) v1(14.68,24.4) v1(14.77,71.74) v1(14.77,63.74) v1(14.78,55.1) v1(14.77,51.74) v1(14.77,47.74) v1(14.77,39.74) v1(14.77,35.74) v1(14.77,19.74) v1(15.77,73.74) v1(15.77,61.74) v1(15.77,57.74) v1(15.77,53.74) v1(15.78,49.93) v1(15.77,45.74) v1(15.77,41.74) v1(15.77,33.74) v1(15.77,25.74) v1(15.77,21.74) v1(15.77,17.74) v1(16.05,65) v1(16.25,59.93) v1(16.45,40.18) v1(16.77,67.74) v1(16.77,61.74) v1(16.78,55) v1(16.77,51.74) v1(16.77,43.74) v1(16.77,31.74) v1(16.77,19.74) v1(17,37.88) v1(17.15,70.45) v1(17.55,35.6) v1(17.68,48.35) v1(17.77,57.74) v1(17.77,53.74) v1(17.85,50) v1(17.85,42.95) v1(17.77,33.74) v1(17.77,25.74) v1(17.77,21.74) v1(17.77,17.74) v1(17.97,60.08) v1(18.2,39.25) v1(18.53,42.03) v1(18.53,36.88) v1(18.77,75.74) v1(18.77,51.74) v1(18.77,43.74) v1(18.77,31.74) v1(18.77,23.74) v1(18.77,19.74) v1(19,55.12) v1(19.05,34.8) v1(19.15,47.73) v1(19.7,36.08) v1(19.77,57.74) v1(19.77,53.74) v1(19.77,45.74) v1(19.77,37.74) v1(19.77,33.74) v1(19.77,29.74) v1(19.77,25.74) v1(19.77,21.74) v1(19.77,17.74) v1(19.93,50) v1(20.43,48.38) v1(20.65,41.38) v1(20.68,39.95) v1(20.77,57.74) v1(20.77,51.74) v1(20.77,31.74) v1(20.77,23.74) v1(20.77,19.74) v1(20.95,35.78) v1(21.03,59.98) v1(21,42.4) v1(21.12,27.08) v1(21.38,38.65) v1(21.7,34.85) v1(21.77,69.74) v1(21.8,62.85) v1(21.8,47.78) v1(21.77,45.74) v1(21.75,40.93) v1(21.77,37.74) v1(21.77,33.74) v1(21.77,29.74) v1(21.77,25.74) v1(21.77,21.74) v1(21.77,17.74) v1(22.3,52.62) v1(22.45,39.75) v1(22.53,36.88) v1(22.57,35.5) v1(22.77,69.74) v1(22.77,51.74) v1(22.8,48.38) v1(22.77,43.74) v1(22.77,27.74) v1(22.77,23.74) v1(22.77,19.74) v1(22.88,37.83) v1(23.25,49.95) v1(23.45,55.35) v1(23.6,34.8) v1(23.77,65.74) v1(23.77,61.74) v1(23.77,57.74) v1(23.77,53.74) v1(23.77,33.74) v1(23.77,31.74) v1(23.77,29.74) v1(23.77,21.74) v1(23.77,17.74) v1(23.9,36.8) v1(24.12,48.8) v1(24.35,47.73) v1(24.32,46.6) v1(24.35,40.78) v1(24.38,44.6) v1(24.38,43.15) v1(24.6,57.58) v1(24.65,35.4) v1(24.68,23.38) v1(24.77,71.74) v1(24.77,67.74) v1(24.77,53.74) v1(24.77,51.74) v1(24.77,27.74) v1(24.78,22.33) v1(24.9,62.85) v1(25,24.43) v1(25.05,50.25) v1(25.1,21.68) v1(25.45,48.85) v1(25.47,34.75) v1(25.77,69.74) v1(25.77,65.74) v1(25.77,61.74) v1(25.8,36.18) v1(25.77,33.74) v1(25.77,29.74) v1(25.77,25.74) v1(25.77,17.74) v1(25.93,46.68) v1(25.95,45.38) v1(25.9,44) v1(25.9,43.25) v1(25.93,42.45) v1(25.88,25.28) v1(25.9,20.95) v1(25.97,47.75) v1(26.35,55.43) v1(26.47,49.95) v1(26.77,71.74) v1(26.77,67.74) v1(26.77,65.74) v1(26.8,46.68) v1(26.8,45.38) v1(26.77,31.74) v1(26.77,27.74) v1(26.77,19.74) v1(26.9,62.85) v1(26.9,20.65) v1(27.1,47.75) v1(27.05,25.65) v1(27.32,53.85) v1(27.28,51.58) v1(27.32,34.78) v1(27.57,48.73) v1(27.55,39.9) v1(27.77,69.74) v1(27.77,61.74) v1(27.82,38.68) v1(27.77,33.74) v1(27.77,29.74) v1(27.77,25.74) v1(27.85,20.78) v1(27.77,17.74) v1(27.95,36.23) v1(28.5,49.95) v1(28.53,41.4) v1(28.55,53.15) v1(28.62,34.78) v1(28.62,25.18) v1(28.6,21.12) v1(28.77,71.74) v1(28.77,67.74) v1(28.77,55.74) v1(28.77,31.74) v1(28.77,27.74) v1(28.77,19.74) v1(29.25,40.7) v1(29.25,24.55) v1(29.2,21.73) v1(29.28,51.68) v1(29.32,49.48) v1(29.28,46.6) v1(29.35,43.55) v1(29.53,35.73) v1(29.62,37.28) v1(29.6,22.35) v1(29.77,69.74) v1(29.77,61.74) v1(29.77,57.74) v1(29.77,33.74) v1(29.77,29.74) v1(29.77,21.74) v1(29.77,17.74) v1(30.18,50.62) v1(30.21,23.96) v1(30.2,22.35) v1(30.32,34.85) v1(30.53,42.65) v1(30.6,52.93) v1(30.55,48.85) v1(30.7,43.5) v1(30.72,38.43) v1(30.65,37.68) v1(30.72,23.95) v1(30.77,71.74) v1(30.77,69.74) v1(30.77,67.74) v1(30.82,62.78) v1(30.77,59.74) v1(30.77,55.74) v1(30.77,31.74) v1(30.8,22.35) v1(31.03,44.08) v1(31.12,51.65) v1(31.1,49.73) v1(31.25,31.28) v1(31.25,30.5) v1(31.25,29.7) v1(31.25,28.85) v1(31.25,28.12) v1(31.25,27.38) v1(31.18,23.95) v1(31.25,22.2) v1(31.25,21.38) v1(31.25,20.58) v1(31.25,19.8) v1(31.25,19) v1(31.25,18) v1(31.25,17.23) v1(31.25,16.43) v1(31.33,36.25) v1(31.28,35.28) v1(31.28,34.5) v1(31.28,33.7) v1(31.28,32.85) v1(31.28,32.05) v1(31.34,26.48) v1(31.34,25.78) v1(31.32,24.9) v1(31.29,24.37) v1(31.53,57.9) v1(31.72,36.98) v1(31.77,71.74) v1(31.77,65.74) v1(31.77,61.74) v1(31.75,37.85) v1(32.5,54.78) v1(32.77,67.74) v1(32.77,59.74) v1(32.77,51.74) v1(32.75,41.68) v1(32.97,43.7) v1(33,39.25) v1(32.98,38.69) v1(33.12,57.73) v1(33.07,40.65) v1(33.18,37.7) v1(33.15,37.18) v1(33.15,36.58) v1(33.45,36.08) v1(33.45,35.28) v1(33.45,34.5) v1(33.45,33.7) v1(33.45,32.8) v1(33.45,32.03) v1(33.45,31.23) v1(33.45,30.38) v1(33.45,29.6) v1(33.45,28.8) v1(33.45,27.93) v1(33.45,27.15) v1(33.45,26.35) v1(33.47,41.7) v1(33.5,38.2) v1(33.53,25.73) v1(33.6,39.18) v1(33.57,25.08) v1(33.57,24.28) v1(33.57,23.5) v1(33.57,22.7) v1(33.57,21.95) v1(33.57,21.15) v1(33.57,20.38) v1(33.57,19.58) v1(33.57,18.78) v1(33.57,17.98) v1(33.57,17.2) v1(33.57,16.4) v1(33.65,42.58) v1(33.77,69.74) v1(33.77,65.74) v1(33.85,63) v1(33.75,55.83) v1(33.77,49.74) v1(34.2,46.88) v1(34.53,18.62) v1(34.77,67.74) v1(34.77,59.74) v1(34.77,51.74) v1(34.78,37.43) v1(34.77,35.74) v1(34.77,31.74) v1(34.77,27.74) v1(34.77,23.74) v1(34.77,19.74) v1(35.32,47.68) v1(35.55,40.03) v1(35.77,69.74) v1(35.77,65.74) v1(35.78,62.03) v1(35.77,49.74) v1(35.75,42.85) v1(35.77,37.74) v1(35.8,36.65) v1(35.77,33.74) v1(35.77,31.74) v1(35.77,29.74) v1(35.77,25.74) v1(35.77,21.74) v1(35.77,17.74) v1(35.95,44.98) v1(35.97,57.88) v1(36.05,55.83) v1(36.77,67.74) v1(36.77,51.74) v1(36.77,43.74) v1(36.77,35.74) v1(36.77,27.74) v1(36.77,19.74) v1(36.95,46.98) v1(37.18,39.43) v1(37.3,61.83) v1(37.32,40.78) v1(37.68,40.15) v1(37.7,23.05) v1(37.77,69.74) v1(37.85,56.1) v1(37.77,49.74) v1(37.77,37.74) v1(37.77,33.74) v1(37.77,21.74) v1(37.77,17.74) v1(37.9,44.95) v1(37.95,42.85) v1(37.97,59.15) v1(38,57.9) v1(37.97,39.08) v1(38.4,42.12) v1(38.77,67.74) v1(38.77,47.74) v1(38.77,43.74) v1(38.77,39.74) v1(38.77,35.74) v1(38.77,19.74) v1(38.97,57.15) v1(39.65,23.05) v1(39.77,69.74) v1(39.77,65.74) v1(39.77,49.74) v1(39.77,25.74) v1(39.77,21.74) v1(39.77,17.74) v1(39.97,59.15) v1(39.97,57.15) v1(40.1,45.18) v1(40.12,43.7) v1(40.1,42.03) v1(40.1,37.8) v1(40.1,34.83) v1(40.77,51.74) v1(40.77,19.74) v1(41.43,66.33) v1(41.43,33.05) v1(41.47,36.23) v1(41.77,73.74) v1(41.77,69.74) v1(41.77,47.74) v1(41.77,41.74) v1(41.77,21.74) v1(41.77,17.74) v1(41.97,59.15) v1(42.03,44.95) v1(42.62,65.03) v1(42.77,75.74) v1(42.77,51.74) v1(42.77,43.74) v1(42.77,39.74) v1(42.77,35.74) v1(42.77,23.74) v1(42.77,19.74) v1(43.12,25.95) v1(43.77,73.74) v1(43.77,69.74) v1(43.77,57.74) v1(43.77,49.74) v1(43.77,41.74) v1(43.77,39.74) v1(43.77,37.74) v1(43.77,33.74) v1(43.77,21.74) v1(43.77,17.74) v1(44.77,75.74) v1(44.77,59.74) v1(44.77,55.74) v1(44.77,51.74) v1(44.77,47.74) v1(44.77,43.74) v1(44.77,35.74) v1(44.77,31.74) v1(44.77,23.74) v1(44.77,19.74) v1(45.77,73.74) v1(45.77,61.74) v1(45.77,57.74) v1(45.77,49.74) v1(45.77,41.74) v1(45.77,37.74) v1(45.77,33.74) v1(45.77,29.74) v1(45.77,27.74) v1(45.77,25.74) v1(45.77,21.74) v1(45.77,17.74) v1(46.77,75.74) v1(46.77,59.74) v1(46.77,55.74) v1(46.77,47.74) v1(46.77,45.74) v1(46.77,39.74) v1(46.77,37.74) v1(46.77,35.74) v1(46.77,33.74) v1(46.77,31.74) v1(46.77,29.74) v1(46.77,23.74) v1(46.77,19.74) v1(47.77,73.74) v1(47.77,57.74) v1(47.77,25.74) v1(47.77,21.74) v1(47.77,17.74) v1(48.77,75.74) v1(48.77,71.74) v1(48.77,59.74) v1(48.77,35.74) v1(48.77,31.74) v1(48.77,27.74) v1(48.77,23.74) v1(48.77,19.74) v1(48.97,69.15) v1(49.77,73.74) v1(49.77,65.74) v1(49.77,61.74) v1(49.77,29.74) v1(49.77,25.74) v1(49.77,21.74) v1(49.77,17.74) v1(49.97,67.15) v1(50.77,75.74) v1(50.77,59.74) v1(50.77,55.74) v1(50.77,51.74) v1(50.85,39.73) v1(50.77,35.74) v1(50.77,31.74) v1(50.77,27.74) v1(50.77,23.74) v1(50.77,19.74) v1(50.88,48.65) v1(50.93,43.68) v1(50.97,69.15) v1(51.77,73.74) v1(51.77,65.74) v1(51.77,61.74) v1(51.77,21.74) v1(51.77,17.74) v1(52.77,75.74) v1(52.77,71.74) v1(52.77,67.74) v1(52.77,59.74) v1(52.77,43.74) v1(52.77,35.74) v1(52.77,31.74) v1(52.77,23.74) v1(52.77,19.74) v1(53.77,69.74) v1(53.77,65.74) v1(53.77,25.74) v1(53.77,21.74) v1(53.77,17.74) v1(54.77,71.74) v1(54.77,67.74) v1(54.77,63.74) v1(54.77,59.74) v1(54.77,55.74) v1(54.77,51.74) v1(54.77,47.74) v1(54.77,43.74) v1(54.77,39.74) v1(54.77,35.74) v1(54.77,31.74) v1(54.77,27.74) v1(54.77,23.74) v1(54.77,19.74) v1(55.77,69.74) v1(55.77,57.74) v1(55.77,53.74) v1(55.77,49.74) v1(55.77,45.74) v1(55.77,41.74) v1(55.77,37.74) v1(55.77,33.74) v1(55.77,29.74) v1(55.77,25.74) v1(55.77,21.74) v1(55.77,17.74) v1(56.77,71.74) v1(56.77,59.74) v1(56.77,55.74) v1(56.77,51.74) v1(56.77,47.74) v1(56.77,43.74) v1(56.77,39.74) v1(56.77,35.74) v1(56.77,31.74) v1(56.77,27.74) v1(56.77,23.74) v1(56.77,19.74) v1(57.77,73.74) v1(57.77,57.74) v1(57.77,53.74) v1(57.77,49.74) v1(57.77,45.74) v1(57.77,41.74) v1(57.77,37.74) v1(57.77,33.74) v1(57.77,29.74) v1(57.77,25.74) v1(57.77,21.74) v1(57.77,17.74)
VDDD: length 1.9
  TOP w0.2: C9.1 31.57,42.45 31.57,40.58 U1.D5
VDDR: length 27.6
  TOP w0.2: C106.1 31.22,37.43 31.22,38.35 31.57,38.7 U1.D1 31.57,39.38
  TOP w0.3: C106.1 C107.1 29.85,36.83 28.66,35.64 v1(27.49,35.64)
  TOP w0.5: L1.1 34.28,43.5 34.28,43.78 C105.1 33.07,47.35 v1(33.12,47.35)
  BOTTOM w0.5: v1(27.49,35.64) 26.7,36.43 26.7,43.96 27.79,45.05 29.4,45.05 31.7,47.35 v1(33.12,47.35)
VDDS: length 43.5
  TOP w0.102: C104.1 27.65,40.65 27.24,40.24 R1.2
  TOP w0.25: v3(29.35,40.18) C102.1 ; v3(23.72,54.6) B1.1 ; C101.1 C103.1 32.52,42.25 v3(31.97,41.7) ; C104.1 v3(27.65,42.43)
  TOP w0.35: C102.1 28.68,40.4 27.75,41.33 C104.1
  LAYER3 w0.2: v3(29.35,40.18) v3(30.78,40.18) ; v3(31.97,39.78) v3(31.97,40.18) v3(31.97,41.7)
  LAYER3 w0.25: v3(31.97,41.7) 31.97,47.98 ; 31.97,47.98 31.97,54 31.38,54.6 v3(23.72,54.6) ; 31.97,47.98 28.15,47.98 27.65,47.48 v3(27.65,42.43)
BP_RESET: length 15.5
  TOP w0.15: R52.1 45.5,56.28 47.85,53.93 47.85,46.48 49.51,44.81 J2.11
BTN1: length 179
  TOP w0.102: R56.2 6.97,63.92 7.32,63.57 7.32,62.2 3.4,58.28 3.4,24.8 4.85,23.35 16.63,23.35 19.07,25.8 19.07,29.19 18.22,30.05 P6.6
  LAYER5 w0.102: P6.6 15.1,31.5 7.38,31.5 4.57,34.3 4.57,59.9 8.8,64.13 51.73,64.13 53.75,62.11 53.75,41.36 J2.16
BTN2: length 142.5
  TOP w0.102: J2.18 53.6,38.67 53.6,58.18 51.42,60.36 51.42,62.72 52.36,63.66 52.68,63.66 R55.2
  LAYER5 w0.102: J2.18 53.96,39.03 53.96,62.19 51.82,64.33 8.72,64.33 4.37,59.99 4.37,34.22 11.08,27.51 P6.1
DCDC: length 3
  TOP w0.2: L1.2 33.88,41.2 32.5,41.2 31.97,40.68 U1.E5
DIO3: length 28.3
  TOP w0.102: v1(30.05,47.2) 30.38,46.88 R6.2
  LAYER5 w0.102: v1(30.05,47.2) 17.88,47.2 11.7,41.03 8.28,41.03 6.98,39.73 J1.15
DIO4: length 26.1
  TOP w0.102: v1(28.32,48.98) R7.1
  LAYER5 w0.102: v1(28.32,48.98) 27.91,49.39 11.81,49.39 10.87,48.45 7.48,48.45 J1.9
DIO8_SDA: length 1.9
  TOP w0.102: P2.5 43.35,28.66 R69.2
DIO8_SDA_T: length 39.5
  TOP w0.102: R69.1 42.1,27.18 v1(42.1,34.55)
  LAYER2 w0.102: v2(31.18,39.38) 30.13,38.33 30.13,35.35 30.02,35.25 v1(29.2,35.25)
  LAYER5 w0.102: v1(29.2,35.25) 28.35,36.1 28.35,40.5 29.05,41.2 41.9,41.2 42.1,41 v1(42.1,34.55)
DIO11: length 44.3
  TOP w0.102: v1(23.15,36.23) 24.73,36.23 25.38,36.87 28.67,36.87 U1.B1
  BOTTOM w0.102: 12.95,65.3 12.93,65.28 12.93,50.4 19.95,43.38 19.95,38.4 22.12,36.23 v1(23.15,36.23) ; 12.95,65.3 R20.1 ; 12.95,65.3 R19.1
DIO11_CS: length 49.1
  LAYER4 w0.102: v1(50.28,53.48) v1(29.4,53.48)
  BOTTOM w0.102: v1(29.4,53.48) 13.95,68.93 12.25,68.93 11.35,68.02 R19.2 ; J2.6 51.32,52.43 v1(50.28,53.48)
DIO11_FLASH_CS: length 49.7
  TOP w0.102: v1(12.97,68.08) 12.97,66.78 13.5,66.25 16.2,66.25 R24.1 U3.1
  LAYER4 w0.102: v1(27.84,52.43) J2.5
  BOTTOM w0.102: v1(12.97,68.08) R20.2 13.35,66.93 v1(27.84,52.43)
DIO12_PICO: length 83.5
  TOP w0.102: U3.5 19.8,64.6 v1(19.8,63.58)
  LAYER3 w0.102: v3(30.78,39.38) 30.35,38.95 v1(28.85,38.95)
  LAYER5 w0.102: v1(19.8,63.58) 20.15,63.93 51.65,63.93 53.55,62.02 53.55,46.24 J2.12
  BOTTOM w0.102: J2.12 50.81,46.12 34.15,46.12 31,42.98 31,41.38 28.85,39.23 v1(28.85,38.95)
DIO18_SCLK: length 20.6
  LAYER2 w0.102: v2(30.78,39.78) 26.25,35.25 26.25,33.08 20.68,27.51 P6.5
DIO21_A10_POCI: length 48
  TOP w0.102: v1(34.62,48.25) 37.22,48.25 39.45,46.03 39.45,32.42 P2.2 ; v1(26.68,48.25) 24.1,48.25 23.8,47.95 23.8,39.58 24.25,39.12 25.12,39.12 25.68,38.58 26.88,38.58 27.78,39.48 29.45,39.48 30.15,40.18 U1.A4
  BOTTOM w0.102: v1(34.62,48.25) v1(26.68,48.25)
DIO24_A7_SCL: length 1.9
  TOP w0.102: P6.2 11.48,31.96 R68.1
DIO24_A7_SCL_T: length 24.4
  TOP w0.102: v1(13,32.58) R68.2
  LAYER2 w0.102: v1(30.55,41.85) 30.97,41.85 31.18,41.65 v2(31.18,40.18)
  LAYER5 w0.102: v1(13,32.58) 19.8,39.38 21.17,39.38 23.65,41.85 v1(30.55,41.85)
GLED: length 50.7
  TOP w0.102: P2.6 45,29.55 45,26.4 43.85,25.25 42.57,25.25 41.35,26.47 R15.2
  BOTTOM w0.102: J2.1 50.74,56.35 53.62,56.35 53.72,56.25 53.72,31.41 53.62,31.31 43.43,31.31 P2.6
LP_RESET: length 14.3
  TOP w0.15: v1(47,48.93) 47,52.78 45.02,54.75 R51.1
  BOTTOM w0.15: J2.10 51.1,47.35 50.02,48.43 48.18,48.43 47.6,49 47.07,49 v1(47,48.93)
POCI: length 78.7
  TOP w0.102: U3.2 17.49,65.62 17.95,65.17 v1(17.95,63.6) ; v1(19.65,61.93) 22.53,61.93 24.6,64 27.82,64 v1(29.62,65.8) ; P2.4 40.79,50.41 v1(36.97,54.23)
  BOTTOM w0.102: v1(17.95,63.6) 19.62,61.93 v1(19.65,61.93) ; v1(29.62,65.8) 36.97,58.45 v1(36.97,54.23) ; J2.14 53.32,41.08 53.32,33.66 52.11,32.45 41.07,32.45 40.79,32.17 P2.4
RF: length 1.9
  TOP w0.3: 32.38,39.38 32.38,38.18 C33.2 32.39,37.46 L33.1
RF_ANT: length 4.6
  TOP w0.15: 32.34,18.63 Z60.1 ; CA2.1 32.35,22.43
  TOP w0.35: Z61.2 32.34,18.63 ; 32.34,19.31 Z60.1
  TOP w0.5: 32.34,21.63 32.34,22.42 32.35,22.43
  TOP w0.68: 32.35,19.33 32.34,19.31
  TOP w0.81: 32.34,21.63 32.35,21.62 32.35,19.33
RF_FILT: length 13.2
  TOP w0.15: 32.38,24.35 32.6,24.12 CR10.2 ; 32.32,23.18 32.35,23.15
  TOP w0.35: L33.2 32.39,36.76 32.39,36.76 C34.2 32.39,36.17 32.38,36.15 32.38,35.58
  TOP w0.81: 32.38,24.35 32.38,35.58
RF_SMA: length 4.6
  TOP w0.15: 31.56,23.18 CA1.2
  TOP w0.5: 31.56,23.18 30.97,23.18 30.96,23.16
  TOP w0.81: J7.1 30.96,23.16
RLED: length 44.4
  TOP w0.102: R14.2 P2.1
  BOTTOM w0.102: J2.3 51.1,53.45 51.69,53.45 51.7,53.46 52.69,53.46 53.52,52.63 53.52,33.57 52.19,32.24 42.9,32.24 42.76,32.1 42.72,32.1 42.07,31.45 42.07,30.13 41.9,29.95 39.28,29.95 38.25,28.93 P2.1
SCL: length 58
  TOP w0.102: P6.4 12.75,28.78 10.53,28.78 10.32,28.98 10.32,35.18 9.55,35.95 7.62,35.95 J1.17 7.78,38.59 7.78,45.17 6.85,46.1 5.9,46.1 5.22,46.78 5.22,58 6.18,58.95 23.72,58.95 R67.1
SCLK: length 60.7
  TOP w0.102: P6.3 12.26,25.75 10.27,25.75 9.4,26.62 9.4,29.18 4.47,34.1 4.47,40.45 6.29,42.27 ; 6.29,42.27 4.78,43.79 4.78,58.33 9.25,62.8 19.7,62.8 20.25,63.35 20.25,65.02 20.15,65.12 U3.6 ; 6.29,42.27 J1.13
SDA: length 118.8
  TOP w0.102: R66.1 23.8,61.03 7.93,61.03 4.98,58.08 4.98,44.57 6.05,43.5 7.05,43.5 7.57,42.98 7.57,41.5 7.07,41 5.78,41 4.72,39.95 4.72,36.31 J1.19
  LAYER5 w0.102: P2.3 42.34,27.12 45.97,27.12 47.6,28.75 47.6,41.7 43.25,46.05 23.6,46.05 10.35,32.8 8.23,32.8 J1.19
WMCU_RESET: length 86.5
  TOP w0.102: v1(25.88,39.2) 25.53,39.55 25.53,39.65 R1.1 C92.1 ; R51.2 v1(34.15,54.75) ; R52.2 41.62,56.96 42.38,57.72 42.38,62.23 43.93,63.78 47.85,63.78 48.88,64.8 48.88,66.15 48.96,66.23 50.32,66.23 52.18,68.08 52.18,70.5 51.45,71.23 CR8.3 50.72,72.25 v1(50.32,72.65) ; U1.A5 30.07,40.58 28.22,42.42 28.22,43.08 26.72,44.58 25.35,44.58 v1(25.32,44.6)
  TOP w0.3: R52.2 R51.2
  BOTTOM w0.102: v1(50.32,72.65) 46.6,72.65 45.2,71.25 33.42,71.25 31.46,73.21 31.46,74.67 P3.11 ; v1(25.88,39.2) 25.32,39.75 v1(25.32,44.6) 25.32,47.95 28.08,50.7 29.23,50.7 33.28,54.75 v1(34.15,54.75)
WMCU_RXD: length 69.7
  TOP w0.102: v1(21.97,42.55) 21.97,42.7 13.57,51.1 7.71,51.1 J1.5 ; P3.7 23.61,74.41 23.61,72.96 20.42,69.78 12.35,69.78 9.55,66.98 v1(9.55,63.73) ; v1(27.93,37.93) 28.57,37.93 30.38,39.73 30.38,39.78
  LAYER2 w0.102: v1(21.97,42.55) 21.97,42.05 23.13,40.9 23.13,39.45 25.02,37.55 27.55,37.55 v1(27.93,37.93)
  BOTTOM w0.102: J1.5 6.95,52.43 8.45,53.93 9.67,53.93 9.95,54.2 9.95,63.33 v1(9.55,63.73)
WMCU_SWDCK: length 69.5
  TOP w0.102: v1(24.9,38.45) 24.9,38.15 25.7,37.35 28.36,37.35 30.38,39.36 30.38,39.38 ; P3.15 36.45,74.75 36.45,73.3 38.03,71.73 47.07,71.73 v1(48.05,70.75) 49.3,70.75 CR8.6 ; v1(46.78,69.5) 46.1,69.5 45.15,68.55 45.15,66.1 42.19,63.15 42.18,63.15 42.13,63.1 R5.2 40.68,63.1 40.47,62.9 v1(40.47,62.25)
  LAYER5 w0.102: v1(40.47,62.25) 40.4,62.33 39.2,62.33 27.4,50.53 v1(25.88,50.53)
  BOTTOM w0.102: v1(46.78,69.5) 46.78,70.48 47.05,70.75 v1(48.05,70.75) ; v1(24.9,38.45) 24.85,38.5 24.85,49.15 25.88,50.18 v1(25.88,50.53)
WMCU_SWDIO: length 71.4
  TOP w0.102: U1.A1 28.48,37.08 24.55,37.08 v1(23.62,38) ; 45.2,69 46.43,70.23 CR8.7 ; 45.2,69 37.5,69 34.02,72.48 34.02,74.64 P3.13 ; 45.2,69 43.88,67.68 43.88,66.23 42.98,66.23 39.85,63.1 R4.2 37.6,63.1 v1(26.21,51.71)
  BOTTOM w0.102: v1(26.21,51.71) 25.66,51.71 24.13,50.18 24.13,49.59 23.43,48.89 23.43,38.2 v1(23.62,38)
WMCU_TXD: length 81.3
  LAYER3 w0.102: v3(31.57,39.78) 31.62,39.73 31.62,38.55 31.2,38.12 31.2,36.8 30.92,36.52 30.92,34.42 30.77,34.28 20.53,34.28 20.42,34.38 20.42,38.59 15.99,43.03 13.72,43.03 10.85,45.9 10.85,47.42 9.62,48.65 7.62,48.65 J1.7
  LAYER4 w0.102: P3.9 26.4,74.66 24.95,74.66 23.84,73.56 23.84,71.88 23.74,71.78 16.18,71.78 5.1,60.7 5.1,51.17 J1.7
WMCU_VDD: length 150.6
  TOP w0.15: R24.2 15.87,67.05 R23.1 ; v1(50.02,67.8) 50.03,67.81 CR8.8 ; 22.43,68.38 v1(22.45,68.4) ; 17.88,68.62 17.9,68.65
  TOP w0.3: v1(52.38,65.01) 50.5,63.13 50.5,60.7 49.09,59.29 44.59,59.29 43.88,60 P4.1
  TOP w0.5: v1(40.25,67.8) 32.88,60.43 29.1,60.43 v1(28.81,60.14) 28.78,60.18 25.97,60.18 25.92,60.23 ; R22.1 22.43,68.38 ; 25.92,60.23 25.92,60.17 25.25,59.5 R67.2 ; 25.92,60.23 25.6,60.55 R66.2 ; J1.1 7.7,56.2 21.03,56.2 21.04,56.2 B1.2 25.78,56.2 v1(26.9,57.33) ; R23.1 14.78,67.95 15.47,68.65 22.2,68.65 v1(22.45,68.4) ; R25.2 17.88,68.62
  BOTTOM w0.5: v1(28.81,60.14) 28.38,59.7 28.38,58.8 v1(26.9,57.33) ; P1.1 54.2,27 54.2,59.15 52.38,60.98 52.38,64.43 52.38,64.43 v1(52.38,65.01) 52.38,65.95 50.53,67.8 v1(50.02,67.8) v1(40.25,67.8)
  BOTTOM w0.55: 24.06,69.31 21.33,72.04 21.33,74.68 P3.5 ; 24.06,69.31 23.36,69.31 v1(22.45,68.4) ; 24.06,69.31 29.1,64.27 29.1,60.43 v1(28.81,60.14)
X32_N: length 5.7
  TOP w0.102: U1.B5 28.8,42.55 Y1.2 C91.1 28.8,44.03 28.32,44.5 R7.2
X32_P: length 5.4
  TOP w0.102: R6.1 30.38,44.5 29.9,44.03 C81.1 Y1.1 29.88,42.73 29.88,41.88 U1.C5
X48_N: length 4.4
  TOP w0.102: C52.1 35.5,39.12 Y2.1 35.3,38.98 34.45,38.98 33.65,39.78 32.38,39.78
X48_P: length 4.6
  TOP w0.102: C53.1 35.74,40.96 Y2.3 34.69,40.96 33.9,40.18 U1.F4
XDS_BOARDID_SCL: length 12.7
  TOP w0.15: U4.1 12.22,73.12 14.4,70.95 20.15,70.95 P3.6
XDS_BOARDID_SDA: length 7.4
  TOP w0.15: U4.3 14.12,73.12 15.32,71.93 18.59,71.93 P3.4
N3109894: length 24.1
  TOP w0.102: v1(39.38,59.75) 39.38,61.43 R4.1
  LAYER5 w0.102: v1(39.38,59.75) 39.38,51.37 48.48,42.27 J2.13
N3109960: length 27.3
  TOP w0.102: v1(41.15,59.88) 41.45,60.18 R5.1
  LAYER5 w0.102: v1(41.15,59.88) 41.15,50.83 48.43,43.55 50,43.55 50.75,42.8 50.75,41.1 49.58,39.93 J2.15
N3110768: length 2.6
  TOP w0.15: SW1.4 5.13,62.25 5.88,63 R56.1
N3110772: length 1.8
  TOP w0.15: SW2.3 53.31,62.23 52.75,62.79 R55.1
N3110876: length 1.3
  TOP w0.15: R15.1 40.75,25.09 40.75,25.09 CR1.2
N3110880: length 1.3
  TOP w0.15: CR2.2 38.25,24.88 38.25,24.88 R14.1
N3111246: length 3.3
  TOP w0.15: C55.1 20.57,67.4 20.25,67.73 R25.1
  TOP w0.25: U3.8 C55.1
N3111262: length 2.8
  TOP w0.15: 22.43,65.88 21.72,65.88 21.47,65.62 U3.7
N3111266: length 2.7
  TOP w0.15: U3.3 16.63,65.12 16.3,65.45 R23.2
N3377070: length 1.6
  TOP w0.15: 32.34,17.43 Z61.1
  TOP w0.35: 32.34,17.43 Z62.1 ANT1.1

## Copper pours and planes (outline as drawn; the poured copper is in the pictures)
GND on TOP (solid shape): 29.46,14.81 30.66,14.81 30.66,15.55 31.66,15.55 31.66,13.52 23.66,13.52 23.66,10.85 29.46,10.85 29.46,11.65 28.46,11.65 28.46,12.86 31.59,12.86 32.11,13.62 32.11,15.55 32.57,15.55 32.57,13.47 31.66,12.15 31.66,11.65 30.66,11.65 30.66,9.85 47.06,9.85 47.06,8.64 21.48,8.64 21.48,14.81 28.46,14.81 28.46,15.55 29.46,15.55
GND on TOP: 32.9,15.55 32.9,23.7 32.93,24.38 31.82,24.38 31.82,23.7 29.32,23.7 29.28,23.68 24.93,23.14 29.28,22.65 29.32,22.6 31.8,22.6 31.8,15.55 0.57,15.54 0.57,58.04 0.83,59.54 1.56,60.88 2.77,64.34 1.56,67.8 0.83,69.14 0.57,70.64 0.57,76.53 0.87,77.24 1.57,77.53 57.07,77.53 57.78,77.24 58.07,76.53 58.07,70.64 57.82,69.14 57.08,67.8 55.87,64.34 57.08,60.88 57.82,59.54 58.07,58.04 58.07,15.54 ; 6 cut-outs
GND on LAYER2, LAYER3: 33.18,15.55 33.18,36.03 31.55,36.03 31.55,23.7 29.32,23.7 29.28,23.68 24.93,23.14 29.28,22.65 29.32,22.6 31.53,22.6 31.53,15.55 0.57,15.54 0.57,58.04 0.83,59.54 1.56,60.88 2.77,64.34 1.56,67.8 0.83,69.14 0.57,70.64 0.57,76.53 0.87,77.24 1.57,77.53 57.07,77.53 57.78,77.24 58.07,76.53 58.07,70.64 57.82,69.14 57.08,67.8 55.87,64.34 57.08,60.88 57.82,59.54 58.07,58.04 58.07,15.54
RF_FILT on TOP: 32.8,24.33 32.8,24.2 32.75,24.15 32.75,23.53 32.6,23.38 32.6,22.98 32.15,22.98 32.15,23.38 32.03,23.5 32.03,24.15 31.97,24.2 31.97,24.33

Small or netless copper shapes (teardrops, artwork), in the pictures only: 1 on BOTTOM, 1 on LAYER4

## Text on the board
Ref Des/Silkscreen Bottom: J1 | 1 | 10 | 21 | 30 | J3 | J4 | 31 | 40 | 11 | 20 | J2 | DIO3 | DIO4 | DIO6 | DIO20 | GLED | RLED | DIO11_F | BPRST | DIO24 | DIO18 | DIO21 | DIO12 | DIO11 | LPRST | DIO8 | SWDIO | SWDCK
User.Comments: Rev. C | Milling tool 2.0 mm TYP | RED | BOTTOM LAYER
Ref Des/Silkscreen Top: 2 | 1 | 6 | 5 | J1 | 10 | 21 | 30 | J3 | J4 | 40 | 31 | 20 | 11 | J2 | DIO24 | BTN2 | SCLK | SCL | BTN1 | DIO18 | Red | DIO21 | POCI | SDA | Green | DIO8 | DIO20 | DIO6 | DIO4 | DIO3 | BTNs/I2C/SPI | CC-ANTENNA-DK | Mount for: | LEDs/I2C/SPI | DIO11_F | BPRST | GLED | RLED | DIO11 | LPRST | DIO12 | SWDIO | SWDCK | GND | 5V | 3V3 | RXD | TXD | nRST | BTN-2 | LP-EM-CC2340R5-YBG | Rev:C | BTN-1
XSECTION_CHART: *  SURFACE - AIR 0 MM | L1 TOP CONDUCTOR - COPPER 0.018 MM | *  DIELECTRIC - FR-4 0.08 MM | L2 LAYER2 CONDUCTOR - COPPER 0.018 MM | L3 LAYER3 CONDUCTOR - COPPER 0.018 MM | *  DIELECTRIC - FR-4 0.78 MM | L4 LAYER4 CONDUCTOR - COPPER 0.018 MM | L5 LAYER5 CONDUCTOR - COPPER 0.018 MM | L6 BOTTOM CONDUCTOR - COPPER 0.018 MM | DESIGN CROSS SECTION CHART | ___________________________ | TOTAL THICKNESS 1.208 MM | 1-6 | 1-2 | 2-3
PAGE_OUTLINE: LP-EM-CC2340R5-YBG
User.28: FIGURE | FINISHED_SIZE | 0.1 | DRILL CHART: TOP to LAYER2 | ALL UNITS ARE IN MILLIMETERS | PLATED | NONSTANDARD | LASER | QTY | 15
User.34: FIGURE | FINISHED_SIZE | 0.2 | 1.05 | 1.1 | 3.2 | 0.9 | DRILL CHART: TOP to BOTTOM | ALL UNITS ARE IN MILLIMETERS | PLATED | NON-PLATED | NONSTANDARD | - | QTY | 722 | 78 | 1 | 4 | 2
User.35: FIGURE | FINISHED_SIZE | 0.1 | DRILL CHART: LAYER2 to LAYER3 | ALL UNITS ARE IN MILLIMETERS | PLATED | NONSTANDARD | LASER | QTY | 10
